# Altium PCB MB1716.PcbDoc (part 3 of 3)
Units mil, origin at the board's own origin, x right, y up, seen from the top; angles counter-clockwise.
Board outline 2806.95 x 1299.21 mil, 4 copper layers (Top Layer, M1, M2, Bottom Layer), stack 62.205 mil thick; 53 components, 45 nets, 298 pads, 399 vias.
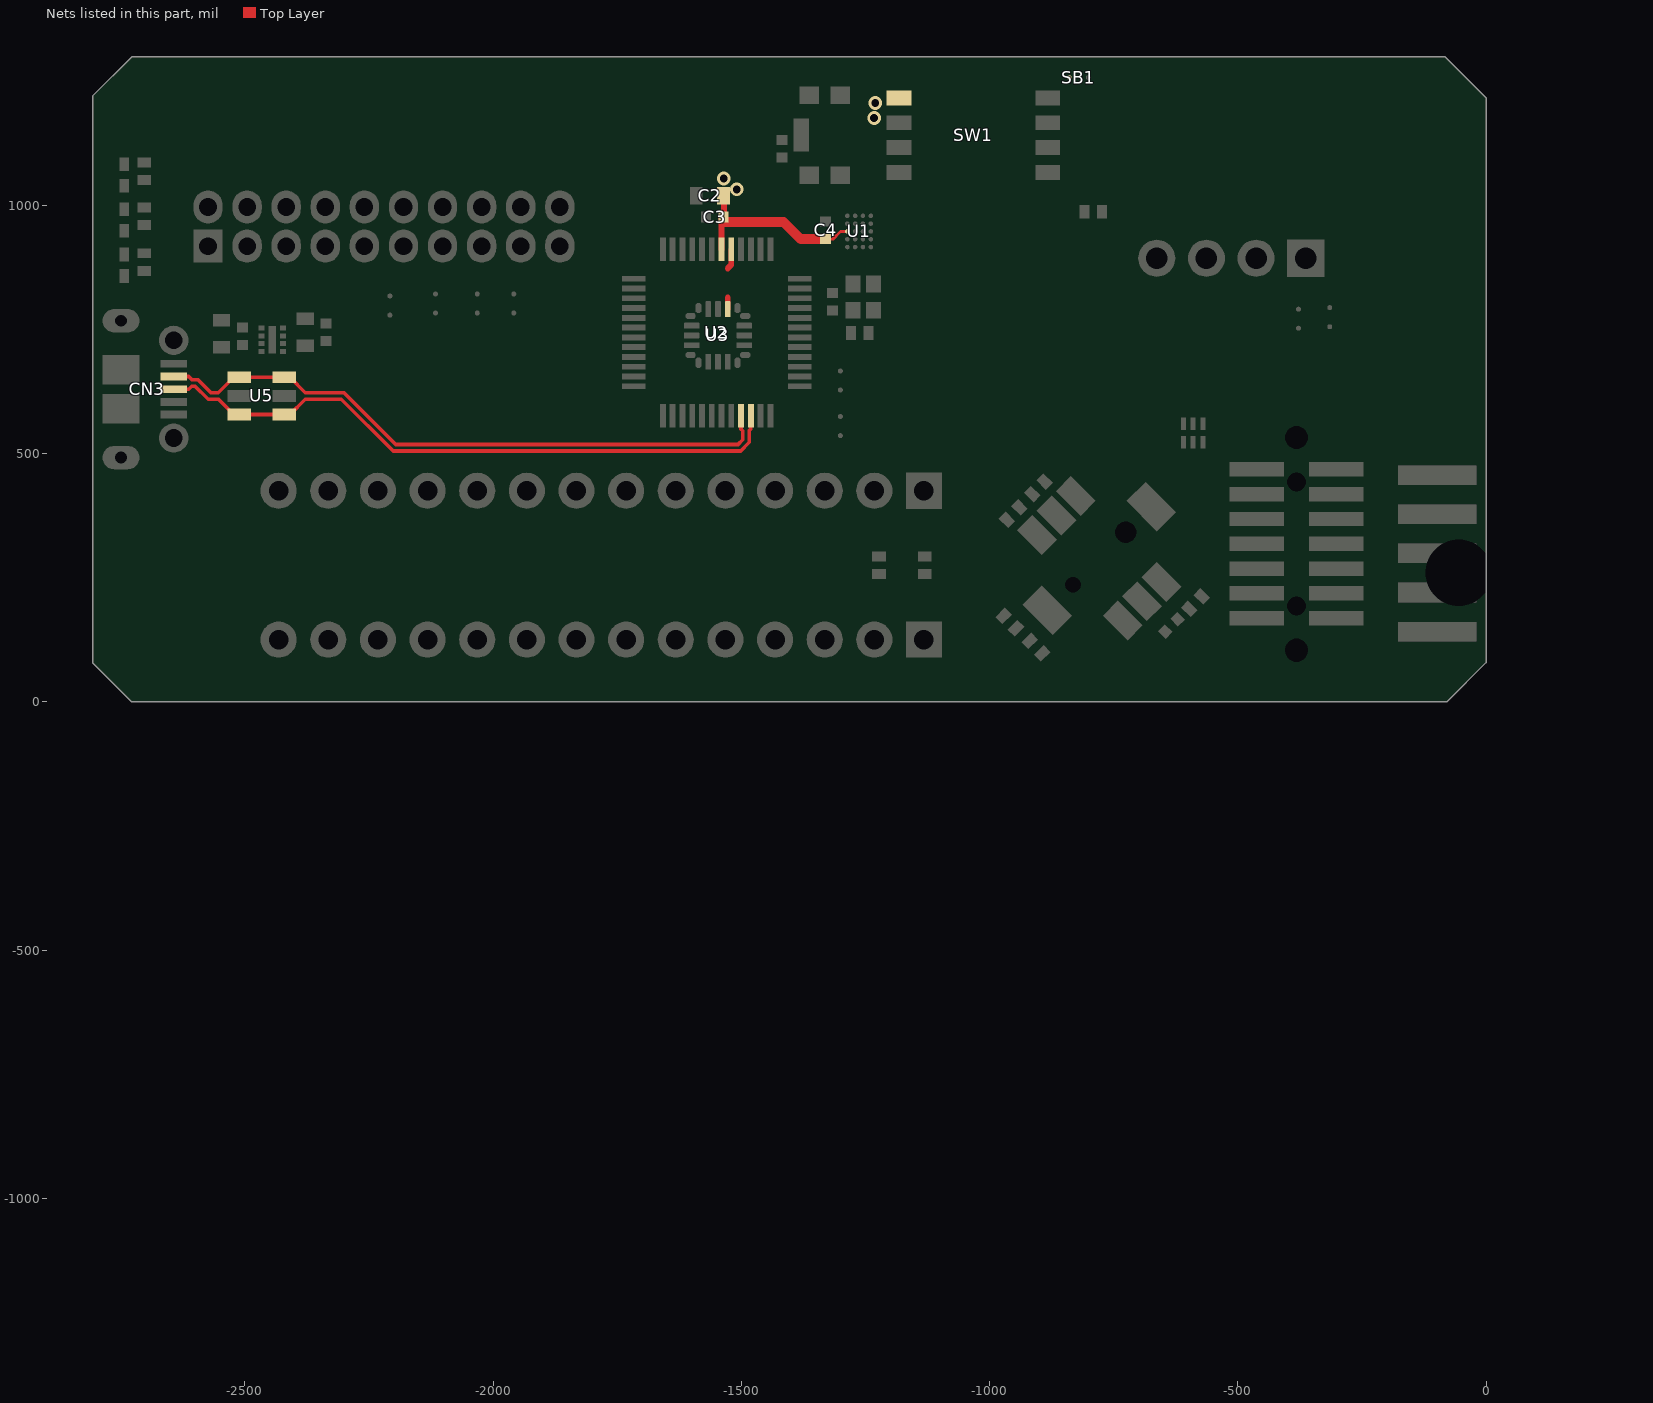
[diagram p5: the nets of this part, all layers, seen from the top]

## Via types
v1: diameter 17.72, hole 9.84, Top Layer to Bottom Layer, tented both sides, 357 vias
v2: diameter 27.56, hole 15.75, Top Layer to Bottom Layer, tented both sides, 31 vias
v3: diameter 7.87, hole 3.94, Top Layer to M1, tented both sides, 11 vias

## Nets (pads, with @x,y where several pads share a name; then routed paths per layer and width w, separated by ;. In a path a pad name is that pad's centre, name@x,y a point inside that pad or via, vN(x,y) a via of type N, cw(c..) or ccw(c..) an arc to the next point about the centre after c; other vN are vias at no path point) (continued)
USBD_N: CN3.2 U2.33 U5.3 U5.4 | length 1282.8
  Top Layer w7.28: CN3.2@-2643.56,655.51 -2613.34,655.51 -2607.14,649.31 -2595.18,649.31 -2568.58,622.72 -2553.9,622.72 -2522.87,653.74 U5.4@-2511.34,653.74 U5.3@-2420.79,653.74 -2409.25,653.74 -2378.45,622.93 -2300.5,622.93 -2196.11,518.54 -1506.92,518.54 -1497.13,528.34 -1497.13,545.93 -1500.7,549.51 U2.33@-1500.7,576.77
USBD_P: CN3.3 U2.34 U5.1 U5.6 | length 1304.2
  Top Layer w7.28: CN3.3@-2643.56,629.92 -2613.34,629.92 -2607.14,636.12 -2600.64,636.12 -2574.05,609.53 -2553.46,609.53 -2522.87,578.94 U5.6@-2511.34,578.94 U5.1@-2420.79,578.94 -2409.25,578.94 -2378.45,609.74 -2305.96,609.74 -2201.57,505.35 -1501.46,505.35 -1483.94,522.87 -1483.94,546.59 -1481.02,549.51 U2.34@-1481.02,576.77
VDD: C2.2 C3.2 C4.2 SB1.2 SW1.5 U1.C4 U2.5 U2.6 U3.2 | length 445.8
  Top Layer w4.72: U1.C4@-1286.59,947.74 U1.C4@-1284.5,947.74
  Top Layer w5.91: C4.2@-1332.52,931.89 -1316.05,931.89 -1300.2,947.74 U1.C4@-1286.59,947.74
  Top Layer w11.81: U2.6@-1540.07,911.42 C3.2@-1540.07,975.67 ; C3.2@-1530.18,971.75 -1534.88,976.46 -1534.88,1011.45 C2.2@-1529.68,1016.65 ; U3.2@-1527.56,791.34 -1527.56,814.88 ; -1527.56,873.39 -1520.39,880.56 U2.5@-1520.39,911.42
  Top Layer w19.68: C3.2@-1535.08,966.85 -1415.04,966.85 -1380.67,932.48 C4.2@-1335.91,932.48
  other v2: -1509.33,1032.48 -1535.59,1054.45 -1232.64,1176.06 -1230.55,1206.46
pads on no net: B2.NPTH1 B2.NPTH2 CN3.4 CN4.0 CN4.2 CN4.5 CN5.0 CN5.8 CN5.9 CN5.10 CN5.11 CN6.9 CN6.10 CN7.8 U2.1 U2.4 U2.8 U2.9 U2.24 U2.25 U2.26 U2.27 U5.5

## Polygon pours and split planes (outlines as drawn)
3V3 on M2 "net" (solid, remove dead copper, pour order 8): -730.67,1202.64 -762.79,1234.76 -797.24,1234.76 -806.93,1225.08 -806.93,1177.93 -755,1126 -748,1126 -730.67,1143.33
3V3 on M2 "net" (solid, remove dead copper, pour order 54): -436.81,780.24 -290.59,780.24 -193.15,682.8 -193.15,514.88 -165.59,487.32 -165.59,226.61 -207.99,184.21 -225.04,184.21 -243.9,203.07 -243.9,241.02 -207.2,277.72 -207.2,460.94 -242.99,496.73 -242.99,667.01 -307.4,731.42 -449.48,731.42
3V3 on M2 "net" (solid, remove dead copper, pour order 26): -2346.69,738.27 -2297.52,738.27 -2287.05,727.8 -2287.05,630.16 -2183.78,526.89 -809.88,526.89 -775,561.77 -775,1194.37 -745.71,1194.37 -730.67,1179.33 -730.67,789.65 -721.06,780.04 -343.7,780.04 -322.36,758.7 -322.36,753.39 -344.13,731.61 -721.06,731.61 -730.67,722.01 -730.67,539.96 -787.68,482.95 -2215.68,482.95 -2352.99,620.26 -2352.99,731.97
VDD on M2 "net" (solid, remove dead copper, pour order 40): -1553.98,1012.8 -1542.91,1001.73 -1500.12,1001.73 -1492.05,1009.8 -1492.05,1153.74 -1462.72,1183.07 -1265.75,1183.07 -1240.79,1158.11 -1223.23,1158.11 -1212.8,1168.54 -1212.8,1216.69 -1219.45,1223.35 -1513.82,1223.35 -1553.98,1183.19
DEMO_3V3 on M2 "net" (solid, remove dead copper, pour order 58): -2699.34,1130.47 -2666.61,1163.19 -1685.71,1163.19 -1614.13,1234.76 -1174.17,1234.76 -1148.5,1209.09 -1148.5,1152.95 -1133.19,1137.64 -1088.82,1137.64 -842.6,891.42 -842.6,579.65 -833.03,570.08 -813.86,570.08 -804.68,579.25 -804.68,920.67 -1148.98,1264.96 -1629.69,1264.96 -1698.66,1195.98 -2681.42,1195.98 -2720.59,1156.81 -2720.59,1142.24 -2711.67,1133.33
5V on M2 "net" (solid, remove dead copper, pour order 44): -790.12,74.76 -738.62,23.27 -320.24,23.27 -265.43,78.07 -237.68,78.07 -218.19,97.56 -218.19,132.05 -227.32,141.18 -308.15,141.18 -317.99,131.34 -317.99,93.15 -346.61,64.53 -691.38,64.53 -732.12,105.27 -732.12,254.49 -752.32,274.69 -790.12,274.68
5V on M2 "net" (solid, remove dead copper, pour order 34): -2243.12,960.76 -2223.12,980.76 -2223.12,1051.19 -2275.59,1103.66 -2660.47,1103.66 -2746.85,1017.28 -2746.85,851.14 -2669.76,774.06 -2626.42,774.06 -2601.73,749.37 -2601.73,400.31 -2451.3,249.88 -932,249.88 -895.12,286.76 -826.12,286.76 -790.12,250.76 -452.12,250.76 -274.57,428.31 -274.57,634.72 -304.84,665 -351.5,665 -360.94,655.55 -360.94,633.74 -318.23,591.02 -318.23,453.65 -466.72,305.16 -750.09,305.16 -793.7,348.76 -924.12,348.76 -975.12,297.76 -2418.04,297.76 -2551.12,430.84 -2551.12,765.25 -2603.78,817.91 -2655.28,817.91 -2699.61,862.24 -2699.61,1000.94 -2640.2,1060.35 -2313.39,1060.35 -2297.4,1044.37 -2297.4,977.09 -2280.32,960 -2240.91,960
GND on M2 "net" (solid, remove dead copper, pour order 60): -2810.59,758.46 -2810.59,1216.83 -2728.21,1299.21 -82.13,1299.21 0,1217.08 0,70.08 -78.35,-8.27 -2719.94,-8.27 -2812.64,84.43 -2812.64,764.29
GND on Bottom Layer "net" (solid, remove dead copper, pour order 62): -2810.59,758.46 -2810.59,1216.83 -2728.21,1299.21 -82.13,1299.21 0,1217.08 0,70.08 -78.35,-8.27 -2719.94,-8.27 -2812.64,84.43 -2812.64,764.29
GND on M1 "net" (solid, remove dead copper, pour order 2): -2810.59,758.46 -2810.59,1216.83 -2728.21,1299.21 -82.13,1299.21 0,1217.08 0,70.08 -78.35,-8.27 -2719.94,-8.27 -2812.64,84.43 -2812.64,764.29
GND on Top Layer "net" (solid, remove dead copper, pour order 0): -2810.59,758.46 -2810.59,1216.83 -2728.21,1299.21 -82.13,1299.21 0,1217.08 0,70.08 -78.35,-8.27 -2719.94,-8.27 -2812.64,84.43 -2812.64,764.29

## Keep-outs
Keep-Out Layer:
  lines w7.87: -1179.6,866.34 cw(c-1140.23,866.34) -1140.23,905.71 -965.04,905.71 ; -1179.6,866.34 -1179.6,594.68 ccw(c-1140.23,594.68) -1140.23,555.31 -965.04,555.32 ccw(c-965.04,594.68) -925.67,594.68 ; -1179.6,866.34 -1179.6,866.34 ; -965.04,905.71 cw(c-965.04,866.34) -925.67,866.34 -925.67,594.69 ; -965.04,905.71 -965.04,905.71 ; -925.67,594.68 -925.67,594.69 ; -2806.95,78.74 -2806.95,748.03 -2806.95,1220.47 -2728.21,1299.21 -82.13,1299.21 0,1217.08 0,1123.07 0,79.21 -79.21,0 -2491.99,0 -2728.21,0 -2806.95,78.74
  text "Keep-Out Layer" at -2526.54,-1039.84 h118.11
  text ".GKO" at -885.02,-1039.84 h118.11
M1-Board Shape:
  lines w7.87: -1179.6,866.34 cw(c-1140.23,866.34) -1140.23,905.71 -965.04,905.71 ; -1179.6,866.34 -1179.6,866.34 ; -1179.6,866.34 -1179.6,594.68 ccw(c-1140.23,594.68) -1140.23,555.31 -965.04,555.32 ccw(c-965.04,594.68) -925.67,594.68 ; -965.04,905.71 cw(c-965.04,866.34) -925.67,866.34 -925.67,594.69 ; -965.04,905.71 -965.04,905.71 ; -925.67,594.68 -925.67,594.69

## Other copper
Top Layer:
  region net 5V: -2668.82,691.06 -2625.55,691.06 -2601.18,715.43 -2601.18,726.85 -2588.31,739.72 -2524.68,739.72 -2520.59,735.63 -2487.44,735.63 -2480.12,742.95 -2460.16,742.95 -2460.16,732.17 -2460.59,731.73 -2471.85,731.73 -2472.56,731.02 -2472.56,728.27 -2471.73,727.44 -2461.14,727.44 -2460.43,726.73 -2460.43,716.57 -2470.94,716.57 -2472.56,714.96 -2472.56,713.46 -2470.12,711.02 -2460.43,711.02 -2460.43,701.34 -2463.82,697.95 -2546.14,697.95 -2577.8,666.3 -2608.07,666.3 -2612.83,671.06 -2669.25,671.06 -2672.01,673.82 -2672.01,688.39 -2668.82,691.57
  region net NetCN2_1: -328.62,784.7 -348.29,804.37 -387.68,804.37 -387.68,877.95 -334.76,930.87 -325.16,930.87 -292.2,897.91 -292.2,793.56 -301.06,784.7
  region net GND: -609.29,607.79 -609.29,587.05 -597.68,575.43 -597.68,547.72 -594.57,544.61 -583.82,544.61 -581.85,546.57 -581.85,576.46 -572.17,586.14 -572.17,608.27 -578.11,614.21 -602.87,614.21
  region net VDD: -1558.03,1061.93 -1558.03,1003.07 -1546.34,991.38 -1546.34,936.26 -1541.93,931.85 -1534.02,931.85 -1531.97,933.9 -1528.66,933.9 -1526.5,931.73 -1517.8,931.73 -1512.01,937.52 -1512.01,982.99 -1492.6,1002.4 -1492.6,1056.38 -1507.56,1071.34 -1548.62,1071.34
  region net GND: -1381.06,974.76 -1381.06,960.24 -1375.71,954.88 -1309.96,954.88 -1305.91,958.94 -1286.3,958.94 -1286.3,967.6 -1286.65,967.95 -1307.87,967.95 -1319.17,979.25 -1376.57,979.25
  region net VDD: -1335.55,942.6 -1313.86,942.6 -1304.25,952.2 -1286.38,952.2 -1286.38,943.9 -1287.01,943.27 -1295.14,943.27 -1315.77,922.64 -1326.06,922.64 -1335.91,932.48
  region net 3V3: -2429.29,727.19 -2405.84,727.19 -2394.92,738.11 -2296.18,738.11 -2289.8,731.73 -2289.8,685.87 -2298.9,676.77 -2347.6,676.77 -2366.3,695.47 -2424.29,695.47 -2429.53,700.71 -2429.53,710.98 -2418.66,711.18 -2417.68,712.17 -2417.68,715.35 -2419.06,716.73 -2428.58,716.73 -2429.29,717.2
  region net 3V3: -451.91,771.91 -390.1,771.91 -383.21,765.02 -370.87,765.02 -363.98,771.91 -363.98,742.87 -374.45,732.4 -445.79,732.4 -455.08,741.69 -455.08,768.74
  region net 5V: -314.84,771.91 -307.95,765.02 -301.06,765.02 -291.65,755.61 -291.65,643.66 -306.38,628.94 -354.76,628.94 -361.54,635.71 -361.54,667.72 -338.94,690.31 -338.94,755.94 -329.02,765.87 -320.89,765.87
  region net DEMO_3V3: -1208.66,1154.17 -1208.66,1182.28 -1206.97,1183.98 -1085.75,1183.98 -1077.2,1175.43 -1077.2,1152.13 -1090.2,1139.13 -1137.8,1139.13 -1149.13,1150.47 -1207.28,1150.47 -1208.27,1151.46 -1208.27,1180.04
  region net GND: -1566.69,915.71 -1566.69,879.17 -1586.5,859.37 -1586.5,837.91 -1563.86,815.28 -1559.33,815.28 -1554.53,810.47 -1554.53,775.39 -1552.83,773.7 -1543.46,773.7 -1540.67,776.5 -1540.67,815.9 -1552.83,828.07 -1552.83,984.49 -1569.8,1001.46 -1569.8,1058.39 -1577.64,1066.22 -1604.88,1066.22 -1631.18,1039.92 -1631.18,977.95 -1598.86,945.63 -1573.98,945.63 -1566.38,938.03 -1566.38,925.04
  region net VDD: -1546.38,940.79 -1546.38,828.58 -1533.5,815.71 -1533.5,775.31 -1532.2,774.02 -1521.14,774.02 -1519.61,775.55 -1519.61,819.69 -1528.86,828.94 -1528.86,862.48 -1512.01,879.33 -1512.01,937.52 -1520.71,937.52 -1526.54,931.69 -1526.54,887.95 -1528.62,885.87 -1531.69,885.87 -1534.06,888.23 -1534.06,936.24 -1538.6,940.79
  pour cut-out: -663.25,846.05 -663.25,916.16 -638.06,941.35 -474.38,941.35 -473.09,940.06 -473.09,847.34 -474.38,846.05
  pour cut-out: -348.78,722.37 -344.29,726.85 -380.35,726.85 -387.36,733.86 -466.1,733.86 -466.1,723.86 -464.61,722.37
  region net NetCN2_1: -400.47,909.65 -400.47,790.69 -391.54,781.75 -335.51,781.75 -328.62,774.86 -318.78,784.7 -301.06,784.7 -301.06,774.86 -292.2,783.72 -292.2,897.91 -325.16,930.87 -379.25,930.87
  pour cut-out: -281.62,755.61 -281.62,899.26 -290.51,908.15 -290.51,753.7 -285.04,748.23
  region net 5V: -175.91,161.5 -240.7,161.5 -262.55,183.35 -353.58,183.35 -356.61,180.31 -356.61,152.99 -302.68,99.06 -231.81,99.06 -208.78,122.09 -168.03,122.09 -168.03,153.62
  pour cut-out: -237.18,492.79 -1.3,492.79 -1.3,167.56 -202.01,167.56 -220.2,167.56 -265.08,212.44 -265.08,464.89
  pour cut-out: -2678.67,1139.95 -2678.67,915.24 -2721.22,915.24 -2721.22,1139.95
  region net GND: -2574.65,749.76 -2521.45,749.76 -2515.71,744.02 -2489.29,744.02 -2485.32,747.99 -2453.7,747.99 -2448.94,743.23 -2437.36,754.8 -2437.36,764.75 -2442.18,769.57 -2442.18,790.05 -2458.78,806.65 -2580.55,806.65 -2583.86,803.35 -2583.86,764.72 -2582.32,763.19
  region net GND: -2405.59,784.86 -2405.59,751.85 -2414.76,742.68 -2433.5,742.68 -2438.46,747.64 -2445.16,740.94 -2445.16,728.46 -2442.44,725.75 -2437.83,725.75 -2431.46,732.13 -2409.8,732.13 -2393.98,747.95 -2314.96,747.95 -2307.17,755.75 -2307.17,791.69 -2329.53,814.06 -2407.95,814.06 -2414.02,807.99
  pour cut-out: -2574.47,1040.5 -1866.8,1040.5 -1852.24,1025.94 -1852.24,874.8 -2613.84,874.8 -2613.84,996.85 -2574.47,996.85
  region net GND: -1269.29,875.39 -1269.29,867.09 -1267.17,864.96 -1255.39,864.96 -1248.23,857.8 -1219.49,857.8 -1210.35,866.93 -1210.35,892.99 -1214.61,892.99 -1229.09,878.5 -1267.13,878.5 -1268.5,877.13
  region net 3V3: -355.51,232.95 -238.23,232.95 -223.78,247.4 -208.82,247.4 -200,238.58 -200,193.62 -207.56,186.06 -227.4,186.06 -243.9,202.56 -356.57,202.56 -357.56,203.54 -357.56,230.91
  region net GND: -2607.14,616.5 -2607.14,596.83 -2616.34,587.64 -2674.02,587.64 -2682.91,596.54 -2692.13,587.32 -2692.13,568.7 -2686.55,568.7 -2674.15,556.3 -2659.33,556.3 -2647.32,544.29 -2643.31,548.31 -2620.96,548.31 -2608.91,560.35 -2589.33,560.35 -2589.33,573.31 -2581.61,581.02
  region net VDD: -820.33,1271.42 -826.63,1277.72 -966.73,1277.72 -1001.97,1242.48 -1227.28,1242.48 -1251.81,1217.95 -1251.81,1172.38 -1237.86,1158.42 -1221.26,1158.42 -1215.59,1164.09 -1215.59,1188.94 -1208.27,1196.26 -986.97,1196.26 -945.71,1237.52 -826.67,1237.52 -820.33,1243.86 -827.22,1250.75 -827.22,1264.53
  region net 3V3: -817,1232 -810.49,1238.51 -810.49,1250.75 -817.38,1257.64 -810.49,1264.53 -810.49,1271.42 -775.42,1271.42 -766,1262 -766,1167 -781.54,1151.46 -908.33,1151.46 -909,1152.13 -909,1181.94 -907,1183.94 -863.06,1183.94 -860,1187 -860,1197 -864,1201 -907,1201 -909,1203 -909,1231.5 -908.5,1232
  text "Top Layer" at -2526.54,-1039.84 h118.11
  text ".GTL" at -885.02,-1039.84 h118.11
M1:
  pour cut-out: -139.45,305.16 -139.45,218.46 2.6,218.46 2.6,305.16
  pour cut-out: -2574.47,1040.5 -1865.8,1040.5 -1865.8,995.58 -1826.09,995.58 -1826.09,918.11 -1865.8,918.11 -1865.8,874.46 -2574.47,874.46 -2574.47,961.42 -2613.84,961.42 -2613.84,996.85 -2574.47,996.85
  text "M1 Layer" at -2526.54,-1039.84 h118.11
  text ".G1" at -885.02,-1039.84 h118.11
M2:
  region net 5V: -2297.4,1023.83 -2297.4,977.09 -2280.32,960 -2240.91,960 -2225.47,975.43 -2225.47,1031.93 -2263.58,1070.04
  pour cut-out: -2432.24,172.05 -1132.24,172.05 -1132.24,125.91 -1087.87,125.91 -1087.87,74.57 -2381.13,74.57 -2381.13,125.39 -2432.24,125.39
  pour cut-out: -2178.9,425.39 -2178.9,477.44 -1092.68,477.44 -1092.68,436.42 -1132.24,436.42 -1132.24,378.73 -2132.24,378.73 -2132.24,425.39
  pour cut-out: -2102.03,1040.5 -1865.8,1040.5 -1865.8,996.85 -1825.47,996.85 -1825.47,918.11 -2104.41,918.11 -2104.41,1036.97
  pour cut-out: -1893.39,714.71 -1893.39,714.52 -1847.05,714.52 -1847.05,737.72 -1884.68,737.72
  pour cut-out: -139.45,305.16 -139.45,218.46 2.6,218.46 2.6,305.16
  pour cut-out: -2527.83,1024.76 -2527.83,1053.11 -2524.25,1056.69 -2319.45,1056.69 -2307.01,1044.25 -2307.01,1010.54 -2312.31,1005.24 -2498.98,1005.24 -2518.5,1024.76
  text "M2 Layer" at -2526.54,-1039.84 h118.11
  text ".G2" at -885.02,-1039.84 h118.11
Bottom Layer:
  pour cut-out: -3.98,498.98 -226.1,498.98 ccw(c-226.1,473.74) -251.33,473.74 -251.33,122 ccw(c-232.28,122) -232.28,102.95 -16.5,102.95 ccw(c-16.5,121.57) 2.13,121.57
  region net 5V: -305.47,101.69 -227.28,101.69 -221.65,107.32 -221.65,128.38 -227.99,134.72 -303.94,134.72 -311.81,126.85 -311.81,107.76 -308.5,104.45
  pour cut-out: -567.97,519.07 -589.49,497.55 -589.49,489.45 -558.98,489.45 -555.63,486.1 -550.35,491.38 -550.35,511.77
  region net 3V3: -241.3,580.55 -241.3,473.74 -204.61,437.05 -168.86,437.05 -168.86,467.76 -176.97,475.87 -184.72,475.87 -201.18,492.32 -201.18,579.8 -209.61,588.23 -233.62,588.23
  pour cut-out: -2613.84,961.42 -2613.84,996.85 -2574.47,996.85 -2574.47,1040.5 -1865.8,1040.5 -1865.8,993.75 -1826.09,993.75 -1826.09,851.02 -1877.99,851.02 -1877.99,874.46 -2613.15,874.46 -2613.15,958.46
  pour cut-out: -2232.24,78.73 -2132.24,78.73 -2132.24,108.89 -2151.3,127.95 -2229.68,127.95 -2232.24,125.39
  pour cut-out: -1167.49,172.05 -1137.95,142.52 -1178.5,101.97 -1178.5,79.13 -1753.78,79.13 -1801.38,126.73 -1801.38,172.05
  pour cut-out: -1591.68,633.08 -1523.08,633.08 -1519.53,629.53 -1519.53,591.14 -1528.5,582.17 -1537.01,590.67 -1581.1,590.67
  region net 3V3: -236.65,240.43 -236.65,193.82 -229.06,186.22 -213.31,186.22 -203.62,195.91 -203.62,238.9 -211.5,246.77 -230.59,246.77 -233.9,243.46
  region net 3V3: -448.27,738.23 -398.23,738.23 -390.91,745.55 -390.91,762.24 -399.92,771.26 -446.73,771.26 -454.61,763.39 -454.61,744.29 -451.3,740.98
  region net 5V: -355.43,629.61 -305.39,629.61 -298.07,636.93 -298.07,653.62 -307.09,662.64 -353.9,662.64 -361.77,654.76 -361.77,635.67 -358.46,632.36
  region net DEMO_3V3: -807.24,575.55 -807.24,625.59 -814.57,632.91 -831.26,632.91 -840.28,623.9 -840.28,577.09 -832.4,569.21 -813.31,569.21 -810,572.52
  region net DEMO_3V3: -1088.5,1180.28 -1138.54,1180.28 -1145.87,1172.95 -1145.87,1156.26 -1136.85,1147.24 -1090.04,1147.24 -1082.17,1155.12 -1082.17,1174.21 -1085.47,1177.52
  region net VDD: -1247.52,1217.05 -1247.52,1167.01 -1240.2,1159.69 -1223.5,1159.68 -1214.49,1168.7 -1214.49,1215.51 -1222.36,1223.39 -1241.46,1223.39 -1244.76,1220.08
  region net 3V3: -799.81,1225.69 -799.81,1175.65 -792.49,1168.33 -775.8,1168.33 -766.78,1177.35 -766.78,1224.16 -774.65,1232.03 -793.75,1232.03 -797.06,1228.72
  region net 5V: -2598.66,733.11 -2598.66,683.07 -2591.34,675.75 -2574.65,675.75 -2565.63,684.76 -2565.63,731.57 -2573.5,739.45 -2592.6,739.45 -2595.91,736.14
  region net 3V3: -2320.24,738.39 -2297.8,738.39 -2288.54,729.13 -2288.54,682.8 -2295.39,675.94 -2344.13,675.94 -2354.88,686.69 -2354.88,704.76 -2322.2,737.44
  region net VDD: -1555.08,1049.94 -1519.69,1014.56 -1501.7,1014.56 -1493.54,1022.72 -1493.54,1040.98 -1526.85,1074.29 -1539.69,1074.29 -1555.27,1058.71 -1555.27,1054.03
  text ".GBL" at -1326.09,-1041.1 h118.11
  text "Bottom Layer" at 300.45,-1041.1 h118.11

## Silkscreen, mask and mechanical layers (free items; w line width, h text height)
Top Overlay:
  lines w3.94: -234.31,217.99 -209.7,229.8 -209.7,206.18 -233.19,217.44
  lines w5: -893.12,640.35 -894.21,639.25 ; -876.12,639.25 -894.21,639.25 ; -894.21,639.25 -894.21,1005.09 ; -894.21,1005.09 -892.78,1005.09 -876.12,988.43 -909.94,988.43 -894.21,1004.15 -894.21,1005.09
  lines w10: -2495.24,175.39 -2495.24,375.39 -1082.24,375.39 -1082.24,300.39 ccw(c-1081.76,275.39) -1082.24,250.39 -1082.24,175.39 -2495.24,175.39
  text "Reset" at -1422.18,1172.38 h55.12 r90
  text "BlueTooth" at -283.37,1106.73 h55.12
  text "STMod+" at -1800.65,1092.77 h55.12
  text "GND" at -112.9,1005.09 h55.12 r90
  text "3V3" at -425.06,814.72 h55.12
  text "5V" at -335.9,814.72 h55.12
  text "IDD" at -871.46,778.58 h55.12
  text "ON" at -738.09,775.4 h55.12
  text "GND" at -467.17,739.07 h55.12 r90
  text "Demo" at -871.46,727.72 h55.12
  text "ON" at -738.09,724.78 h55.12
  text "BT_RX" at -622.29,714.57 h55.12 r90
  text "BT_TX" at -541.69,715.04 h55.12 r90
  text "RXSL" at -871.46,676.87 h55.12
  text "ON" at -738.09,674.16 h55.12
  text "MB1716A" at -146.26,631.57 h80 r90
  text "32K" at -871.46,626.72 h55.12
  text "OFF" at -758,624.23 h55.12
  text "STDC14" at -467.17,590.59 h55.12
  text "BTB_10" at -169.99,513.43 h55.12
  text "NRST" at -1169.21,482.46 h55.12
  text "D8" at -2412.6,481.85 h55.12 r90
  text "D7" at -2315.51,481.85 h55.12 r90
  text "D6" at -2219.57,481.85 h55.12 r90
  text "D5" at -2116.46,481.85 h55.12 r90
  text "GND" at -1816.69,481.85 h55.12 r90
  text "5V" at -1715.39,481.85 h55.12 r90
  text "D4" at -1611.65,481.85 h55.12 r90
  text "D3" at -1512.72,481.85 h55.12 r90
  text "D2" at -1416.81,481.85 h55.12 r90
  text "D1" at -1321.65,481.85 h55.12 r90
  text "D0" at -1221.38,481.85 h55.12 r90
  text "CLK" at -181,344.8 h55.12 r90
  text "DIP28 Arduino-compatible pinout" at -2422.01,261.57 h70.87
  text "DIO" at -181.1,260.79 h55.12 r90
  text "UP" at -996.12,259.76 h55.12 r90
  text "5V" at -181.1,118.86 h55.12 r90
  text "J" at -2527.83,64.33 h500 r90
  text "5V" at -1971.38,31.5 h55.12 r45
  text "A1" at -1572.87,32 h55.12 r45
  text "D9" at -2486.61,30.31 h55.12 r45
  text "A2" at -1471.06,30.34 h55.12 r45
  text "A3" at -1385.04,30.78 h55.12 r45
  text "A4" at -1282.32,30.31 h55.12 r45
  text "A5" at -1192.8,31.14 h55.12 r45
  text "A0" at -1683.46,30.27 h55.12 r45
  text "D11" at -2297.01,14.37 h55.12 r45
  text "D10" at -2399.72,12.64 h55.12 r45
  text "D12" at -2195.2,12.71 h55.12 r45
  text "D13" at -2098.66,13.14 h55.12 r45
  text "GND" at -1816.61,11.93 h55.12 r45
  text "Top Overlay" at -2526.54,-1039.84 h118.11
  text ".GTO" at -885.02,-1039.84 h118.11
Bottom Overlay:
  text "E" at -498.27,1039.84 h400
  text "S" at -200.63,1015.16 h400
  text "I" at -1772.72,632.68 h400
  text "C" at -620.59,613.35 h400
  text "H" at -353.62,609.84 h400
  text "G" at -2232.87,578.23 h400
  text "F" at -1992.24,578.23 h400
  text "GND" at -1847.68,489.68 h55.12 r270
  text "NRST" at -1083.9,488.35 h55.12
  text "D8" at -2447.56,487.68 h55.12 r270
  text "D7" at -2345.24,487.68 h55.12 r270
  text "D6" at -2244.88,487.68 h55.12 r270
  text "D5" at -2146.61,487.68 h55.12 r270
  text "5V" at -1747.32,487.68 h55.12 r270
  text "D4" at -1640.94,487.68 h55.12 r270
  text "D3" at -1548.03,487.68 h55.12 r270
  text "D1" at -1346.69,487.68 h55.12 r270
  text "D0" at -1251.1,487.68 h55.12 r270
  text "D2" at -1450,486.81 h55.12 r270
  text "3V3" at -198.31,443.58 h62.99
  text "NRST" at -198.31,360.32 h62.99
  text "TX" at -198.31,282.64 h62.99
  text "RX" at -198.31,206.1 h62.99
  text "GND" at -198.31,123.94 h62.99
  text "D9" at -2408.98,30.32 h55.12
  text "D10" at -2298.74,30.32 h55.12
  text "D13" at -1994.92,30.32 h55.12
  text "5V" at -1907.99,30.32 h55.12
  text "GND" at -1687.56,30.32 h55.12
  text "A0" at -1607.8,30.32 h55.12
  text "A3" at -1305.79,30.32 h55.12
  text "A5" at -1106.85,30.32 h55.12
  text "D11" at -2200.16,29.61 h55.12
  text "D12" at -2100.67,29.61 h55.12
  text "A1" at -1511.02,29.61 h55.12
  text "A2" at -1407.05,29.61 h55.12
  text "A4" at -1204.38,29.61 h55.12
  text ".GBO" at -1326.09,-1041.1 h118.11
  text "Bottom Overlay" at 300.45,-1041.1 h118.11
Top Paste:
  text "Top Paste" at -2526.54,-1039.84 h118.11
  text ".GTP" at -885.02,-1039.84 h118.11
Bottom Paste:
  text ".GBP" at -1326.09,-1041.1 h118.11
  text "Bottom Paste" at 300.45,-1041.1 h118.11
Top Solder:
  region: -84.61,1289.75 -84.61,622.95 -11.63,622.95 -11.63,1216.77
  text "Top Solder" at -2526.54,-1039.84 h118.11
  text ".GTS" at -885.02,-1039.84 h118.11
Bottom Solder:
  region: -158.46,1291.34 -158.46,622.95 -11.63,622.95 -11.63,1216.77 -86.2,1291.34
  text ".GBS" at -1326.09,-1041.1 h118.11
  text "Bottom Solder" at 300.45,-1041.1 h118.11
M1-Board Shape:
  lines w7.87: 0,79.57 0,247.95 -110.24,247.95 cw(c-110.24,259.76) -110.24,271.57 0,271.57 ; -2806.95,78.74 -2728.21,0 ; -2806.95,78.74 -2806.95,748.03 ; -2806.95,78.74 -2728.21,0 ; -2806.95,78.74 -2806.95,748.03 ; -2806.95,748.03 -2806.95,1220.47 ; -2806.95,748.03 -2806.95,1220.47 ; -2806.95,1220.47 -2728.21,1299.21 ; -2806.95,1220.47 -2728.21,1299.21 ; -2728.21,0 -2491.99,0 ; -2728.21,0 -2491.99,0 ; -2728.21,1299.21 -82.13,1299.21 ; -2728.21,1299.21 -82.13,1299.21 ; -2491.99,0 -79.21,0 ; -2491.99,0 -79.21,0 ; -82.13,1299.21 0,1217.08 ; -82.13,1299.21 0,1217.08 ; -79.21,0 0,79.21 -79.21,0 ; 0,271.57 0,1217.08 ; 0,271.57 0,1217.08
M2-Board Dimensions:
  text "M2-Board Dimensions" at -2526.54,-1039.84 h118.11
  text ".GM2" at -885.02,-1039.84 h118.11
M14-Top Assembly:
  lines w7.87: -79.21,0 0,0 0,79.21
  text "M14-Top Assembly" at -2526.54,-1039.84 h118.11
  text ".GM14" at -885.02,-1039.84 h118.11
M15-Bottom Assembly:
  text ".GM15" at -1326.09,-1041.1 h118.11
  text "M15-Bottom Assembly" at 300.45,-1041.1 h118.11
Drill Drawing:
  drawing of 548 lines, arcs and shapes, not listed
  text "PCB SPECIFICATIONS :" at -2936.81,3974.87 h118.11
  text "PCB : TYPE 3" at 2869.95,3968.09 h118.11
  text "A.   MATERIAL :" at -2936.81,3817.39 h118.11
  text "FR-4" at -1421.06,3817.39 h118.11
  text "TG-170" at -771.46,3817.39 h118.11
  text "X  TG-150" at -52.95,3817.39 h118.11
  text "TG-140" at 576.97,3817.39 h118.11
  text "ASPECT-RATIO, AXE Z :" at 2869.95,3751.55 h118.11
  text "B.   MATERIAL FAMILY :" at -2936.81,3699.28 h118.11
  text "N/A" at -1421.06,3699.28 h118.11
  text "C.   SOLDERMASK COLOR :" at -2936.81,3581.17 h118.11
  text "GREEN" at -1421.06,3581.17 h118.11
  text "WHITE" at -766.18,3580.35 h118.11
  text "X   BLUE" at -52.95,3581.17 h118.11
  text "BLACK" at 576.97,3581.17 h118.11
  text "6:1 to 8:1 / LEVEL \"B\"" at 2870.68,3485.9 h118.11
  text "D.   SILKSCREEN COLOR :" at -2936.81,3463.06 h118.11
  text "X   WHITE" at -1421.06,3463.06 h118.11
  text "YELLOW" at -771.46,3463.06 h118.11
  text "BLACK" at -52.95,3463.06 h118.11
  text "Blue ink PANTONE 2955" at 576.97,3463.06 h118.11
  text "E.   SURFACE FINISH :" at -2936.81,3344.95 h118.11
  text "X  ENIG" at -1421.06,3344.95 h118.11
  text "IMMERSION SILVER" at -771.46,3344.95 h118.11
  text "IMMERSION TIN" at 576.97,3344.95 h118.11
  text "MINIMUM PARAMETERS" at 2871.74,3265.39 h118.11
  text "HASL" at -1421.06,3226.84 h118.11
  text "HASL (PB-FREE)" at -771.46,3226.84 h118.11
  text "GOLDEN FINGER" at 576.97,3226.84 h118.11
  text "F.   IMPEDANCE CONTROL :" at -2936.81,3108.73 h118.11
  text "NO" at -1421.06,3108.73 h118.11
  text "X YES  (SEE IMPEDANCE TABLE FOR DETAIL INFORMATION)" at -794,3109 h118.11
  text "DEFAULT" at 2871.74,3048.86 h118.11
  text "G.   THROUGH VIA :" at -2936.81,2990.62 h118.11
  text "PLUG THE VIAS WHICH ARE COVERED WITH SOLDERMASK ONE OR TWO SIDE." at -1421.06,2990.62 h118.11
  text "PLUG MATERIAL :" at -1421.06,2872.51 h118.11
  text "X  SOLDERMASK" at -417.13,2872.51 h118.11
  text "NON-CONDUCTIVE EPOXY." at 576.97,2872.51 h118.11
  text "TRACKS : 0.12mm           / GAPS : 0.12mm" at 2871.74,2822.48 h118.11
  text "H.   STACK-UP :" at -2936.81,2754.4 h118.11
  text "SEE LAYER STACK-UP SEQUENCE FOR OVERALL THICKNESS." at -1421.06,2754.4 h118.11
  text "Symbol" at 1223.73,2449.76 h85.04
  text "Count" at 1557.06,2449.76 h85.04
  text "Hole Size" at 1904.72,2449.76 h85.04
  text "Plated" at 2548.07,2449.76 h85.04
  text "Hole Type" at 2840.73,2449.76 h85.04
  text "Drill Layer Pair" at 3266.61,2449.76 h85.04
  text "Via/Pad" at 4073.82,2449.76 h85.04
  text "Pad Shape" at 4422.92,2449.76 h85.04
  text "Template" at 4878.84,2449.76 h85.04
  text "IMPEDANCE TABLE     USB" at -2945.61,2402.28 h118.11
  text "1" at 1557.06,2302.71 h70.87
  text "31.50mil (0.80mm)" at 1904.72,2302.71 h70.87
  text "NPTH" at 2548.07,2302.71 h70.87
  text "Round" at 2840.73,2302.71 h70.87
  text "Top Layer - Bottom Layer" at 3266.61,2302.71 h70.87
  text "Pad" at 4073.82,2302.71 h70.87
  text "Rounded" at 4422.92,2302.71 h70.87
  text "c0hn80m85p1000" at 4878.84,2302.71 h70.87
  text "LAYER" at -2778.28,2205.42 h118.11
  text "TRACE" at -2138.52,2205.42 h118.11
  text "SPACING" at -1725.13,2205.42 h118.11
  text "IMPEDANCE" at -1193.64,2205.42 h118.11
  text "IMPEDANCE" at -524.35,2205.42 h118.11
  text "TOL." at 213.84,2205.43 h118.11
  text "1" at 1557.06,2155.66 h70.87
  text "43.31mil (1.10mm)" at 1904.72,2155.66 h70.87
  text "NPTH" at 2548.07,2155.66 h70.87
  text "Round" at 2840.73,2155.66 h70.87
  text "Top Layer - Bottom Layer" at 3266.61,2155.66 h70.87
  text "Pad" at 4073.82,2155.66 h70.87
  text "Rounded" at 4422.92,2155.66 h70.87
  text "c0hn110m115p1000" at 4878.84,2155.66 h70.87
  text "(mm)" at -1594.23,2107.98 h98.43
  text "(mm)" at -2059.78,2106.02 h98.43
  text "(Single ended)" at -1173.95,2097.16 h98.43
  text "(Differential)" at -475.13,2097.16 h98.43
  text "1" at 1557.06,2008.61 h70.87
  text "133.86mil (3.40mm)" at 1904.72,2008.61 h70.87
  text "NPTH" at 2548.07,2008.61 h70.87
  text "Slot" at 2840.73,2008.61 h70.87
  text "Top Layer - Bottom Layer" at 3266.61,2008.61 h70.87
  text "Pad" at 4073.82,2008.61 h70.87
  text "Rounded" at 4422.92,2008.61 h70.87
  text "c0hn340_60m345" at 4878.84,2008.61 h70.87
  text "0.185" at -2100.13,1950.5 h118.11
  text "NA" at -973.17,1950.5 h118.11
  text "0.15" at -1626.71,1949.52 h118.11
  text "90 ohm" at -396.39,1949.52 h118.11
  text "+/- 10%" at 154.79,1949.52 h118.11
  text "TOP" at -2926.71,1948.93 h118.11
  text "2" at 1557.06,1861.56 h70.87
  text "23.62mil (0.60mm)" at 1904.72,1861.56 h70.87
  text "PTH" at 2548.07,1861.56 h70.87
  text "Slot" at 2840.73,1861.56 h70.87
  text "Top Layer - Bottom Layer" at 3266.61,1861.56 h70.87
  text "Pad" at 4073.82,1861.56 h70.87
  text "Rounded" at 4422.92,1861.56 h70.87
  text "r190_120h60_130r100m195_125" at 4878.84,1861.56 h70.87
  text "2" at 1557.06,1714.51 h70.87
  text "38.19mil (0.97mm)" at 1904.72,1714.51 h70.87
  text "NPTH" at 2548.07,1714.51 h70.87
  text "Round" at 2840.73,1714.51 h70.87
  text "Top Layer - Bottom Layer" at 3266.61,1714.51 h70.87
  text "Pad" at 4073.82,1714.51 h70.87
  text "Rounded" at 4422.92,1714.51 h70.87
  text "c0hn97m102" at 4878.84,1714.51 h70.87
  text "2" at 1557.06,1567.46 h70.87
  text "46.85mil (1.19mm)" at 1904.72,1567.46 h70.87
  text "NPTH" at 2548.07,1567.46 h70.87
  text "Round" at 2840.73,1567.46 h70.87
  text "Top Layer - Bottom Layer" at 3266.61,1567.46 h70.87
  text "Pad" at 4073.82,1567.46 h70.87
  text "Rounded" at 4422.92,1567.46 h70.87
  text "c0hn119m124" at 4878.84,1567.46 h70.87
  text "4" at 1557.06,1420.41 h70.87
  text "43.31mil (1.10mm)" at 1904.72,1420.41 h70.87
  text "PTH" at 2548.07,1420.41 h70.87
  text "Round" at 2840.73,1420.41 h70.87
  text "Top Layer - Bottom Layer" at 3266.61,1420.41 h70.87
  text "Pad" at 4073.82,1420.41 h70.87
  text "(Mixed)" at 4422.92,1420.41 h70.87
  text "(Mixed)" at 4878.84,1420.41 h70.87
  text "11" at 1557.06,1273.36 h70.87
  text "3.94mil (0.10mm)" at 1904.72,1273.36 h70.87
  text "PTH" at 2548.07,1273.36 h70.87
  text "Round" at 2840.73,1273.36 h70.87
  text "Top Layer - M1" at 3266.61,1273.36 h70.87
  text "Via" at 4073.82,1273.36 h70.87
  text "Rounded" at 4422.92,1273.36 h70.87
  text "v20h10m0" at 4878.84,1273.36 h70.87
  text "22" at 1557.06,1126.31 h70.87
  text "35.43mil (0.90mm)" at 1904.72,1126.31 h70.87
  text "PTH" at 2548.07,1126.31 h70.87
  text "Round" at 2840.73,1126.31 h70.87
  text "Top Layer - Bottom Layer" at 3266.61,1126.31 h70.87
  text "Pad" at 4073.82,1126.31 h70.87
  text "(Mixed)" at 4422.92,1126.31 h70.87
  text "(Mixed)" at 4878.84,1126.31 h70.87
  text "28" at 1557.06,979.26 h70.87
  text "39.37mil (1.00mm)" at 1904.72,979.26 h70.87
  text "PTH" at 2548.07,979.26 h70.87
  text "Round" at 2840.73,979.26 h70.87
  text "Top Layer - Bottom Layer" at 3266.61,979.26 h70.87
  text "Pad" at 4073.82,979.26 h70.87
  text "Rounded" at 4422.92,979.26 h70.87
  text "(Mixed)" at 4878.84,979.26 h70.87
  text "31" at 1557.06,832.21 h70.87
  text "15.75mil (0.40mm)" at 1904.72,832.21 h70.87
  text "PTH" at 2548.07,832.21 h70.87
  text "Round" at 2840.73,832.21 h70.87
  text "Top Layer - Bottom Layer" at 3266.61,832.21 h70.87
  text "Via" at 4073.82,832.21 h70.87
  text "Rounded" at 4422.92,832.21 h70.87
  text "v70h40m0mx0" at 4878.84,832.21 h70.87
  text "357" at 1557.06,685.16 h70.87
  text "9.84mil (0.25mm)" at 1904.72,685.16 h70.87
  text "PTH" at 2548.07,685.16 h70.87
  text "Round" at 2840.73,685.16 h70.87
  text "Top Layer - Bottom Layer" at 3266.61,685.16 h70.87
  text "Via" at 4073.82,685.16 h70.87
  text "Rounded" at 4422.92,685.16 h70.87
  text "(Mixed)" at 4878.84,685.16 h70.87
  text "462 Total" at 1557.06,538.11 h70.87
  text "Slot definitions :" at 1223.73,435.18 h70.87
  text "Routed Path Length" at 1707.61,435.18 h70.87
  text "= Calculated from tool start centre position to tool end centre position." at 2306.99,435.18 h70.87
  text "Hole Length" at 1707.61,376.36 h70.87
  text "= Routed Path Length + Tool Size = Slot length as defined in the PCB layout" at 2084.51,376.36 h70.87
  text "Layer" at 1227.5,-71.5 h60
  text "Name" at 1637.41,-71.5 h60
  text "Material" at 2567.16,-71.5 h60
  text "Thickness" at 3426.92,-71.5 h60
  text "Constant" at 4076.76,-71.5 h60
  text "Board Layer Stack" at 4646.62,-71.5 h60
  text "Top Overlay" at 1637.41,-191.5 h60
  text "Top Solder" at 1637.41,-311.5 h60
  text "Solder Resist" at 2567.16,-311.5 h60
  text "0.015mm" at 3426.92,-311.5 h60
  text "3.5" at 4076.76,-311.5 h60
  text "1" at 1227.5,-431.5 h60
  text "Top Layer" at 1637.41,-431.5 h60
  text "Copper" at 2567.16,-431.5 h60
  text "0.035mm" at 3426.92,-431.5 h60
  text "Dielectric 1" at 1637.41,-551.5 h60
  text "FR-4" at 2567.16,-551.5 h60
  text "0.220mm" at 3426.92,-551.5 h60
  text "4.2" at 4076.76,-551.5 h60
  text "2" at 1227.5,-671.5 h60
  text "M1" at 1637.41,-671.5 h60
  text "Copper" at 2567.16,-671.5 h60
  text "0.035mm" at 3426.92,-671.5 h60
  text "Dielectric 3" at 1637.41,-791.5 h60
  text "1.000mm" at 3426.92,-791.5 h60
  text "4.2" at 4076.76,-791.5 h60
  text "3" at 1227.5,-911.5 h60
  text "M2" at 1637.41,-911.5 h60
  text "Copper" at 2567.16,-911.5 h60
  text "0.035mm" at 3426.92,-911.5 h60
  text "Dielectric 2" at 1637.41,-1031.5 h60
  text "0.220mm" at 3426.92,-1031.5 h60
  text "4.2" at 4076.76,-1031.5 h60
  text "Drill Drawing" at -2526.54,-1039.84 h118.11
  text ".DRL" at -885.02,-1039.84 h118.11
  text "4" at 1227.5,-1151.5 h60
  text "Bottom Layer" at 1637.41,-1151.5 h60
  text "Copper" at 2567.16,-1151.5 h60
  text "0.035mm" at 3426.92,-1151.5 h60
  text "Bottom Solder" at 1637.41,-1271.5 h60
  text "Solder Resist" at 2567.16,-1271.5 h60
  text "0.015mm" at 3426.92,-1271.5 h60
  text "3.5" at 4076.76,-1271.5 h60
  text "Bottom Overlay" at 1637.41,-1391.5 h60
M20-Top Title Box:
  circle w10: c544.49,-1304.43 r51.18
  region: -25.51,-1347.47 -448.98,-1347.47 -409.87,-1249.33 -100.51,-1249.33 -82.85,-1219.43 4.1,-1319.76
  region: 525.79,-1019.54 -85.51,-1019.54 -112.85,-1089.43 -160.51,-1137.66 -215.51,-1064.43 -215.51,-999.43 -170.51,-944.43 -113.98,-929.54 525.79,-929.54
  lines w10: -409.87,-1249.33 -63.74,-1249.33 -184.45,-1110.05 cw(c-113.43,-1033.52) -103.98,-929.54 556.02,-929.54 526.02,-1019.54 ; -279.41,-919.81 cw(c-183.89,-958.01) -174.58,-855.56 ; -277.87,-918.53 -448.98,-1347.47 311.75,-1347.47 ccw(c321.54,-1239.82) 421.91,-1279.97 ; -209.37,-1073.44 4.1,-1319.76 ; -199.37,-1073.44 9.49,-1314.43 ; -199.37,-1063.44 9.49,-1304.43 ; -195.51,-1019.54 316.02,-1019.54 ; -194.37,-1058.44 14.49,-1299.43 ; -189.37,-1053.44 19.49,-1294.43 ; -184.37,-1048.44 24.49,-1289.43 ; -179.37,-1043.44 29.49,-1284.43 ; -177.22,-966.58 31.64,-1207.57 ; -174.53,-855.57 591.21,-855.57 421.94,-1279.87 ; -174.37,-1038.44 32.34,-1276.96 ; -174.37,-1028.44 34.49,-1269.43 ; -174.37,-1018.44 34.49,-1259.43 ; -174.37,-983.44 34.49,-1224.43 ; -169.37,-1013.44 39.49,-1254.43 ; -169.37,-998.44 39.49,-1239.43 ; -115.37,-1249.86 ccw(c-111.23,-1228.78) -99.51,-1210.79 ; -72.59,-1019.01 ccw(c-73.61,-1041.35) -86.62,-1059.54 6.49,-1166.97 cw(c-64.53,-1243.5) -35.69,-1343.84 ; 174.7,-1339.43 288.46,-1009.54 ; 183.46,-1337.47 296.42,-1009.88 ; 188.46,-1337.47 301.42,-1009.88 ; 198.46,-1337.47 311.42,-1009.88 ; 208.46,-1337.47 321.42,-1009.88 ; 218.46,-1337.47 331.42,-1009.88 ; 228.46,-1337.47 341.42,-1009.88 ; 238.46,-1337.47 351.42,-1009.88 ; 248.46,-1337.47 361.42,-1009.88 ; 258.46,-1337.47 371.42,-1009.88 ; 266.67,-1339.43 380.42,-1009.54 ; 380.42,-1019.54 525.79,-1019.54 ; 499.49,-1019.43 529.49,-929.43 ; 506.02,-1019.54 536.02,-929.54 ; 516.02,-1019.54 546.02,-929.54
  lines w11.81: -2880.88,-1500.47 662.42,-1500.47 662.42,-713.07 -2880.88,-713.07 ; -2880.88,-1303.62 -518.68,-1303.62 ; -2880.88,-1106.77 -518.68,-1106.77 ; -2880.88,-909.92 -518.68,-909.92 ; -2880.87,-1500.47 -2880.87,-713.07 ; -1306.08,-1500.47 -1306.08,-909.92 ; -518.68,-1500.47 -518.68,-713.07 ; 174.7,-1339.43 266.67,-1339.43
  text "Project: '.Board_Name'" at -2841.5,-839.69 h118.11
  text "Layer:" at -2841.5,-1039.84 h118.11
  text "Gerber:" at -1267.14,-1039.84 h118.11
  text "Variant: '.VariantName'" at -2841.5,-1236.69 h118.11
  text "Ref: MB1716" at -1262.14,-1236.69 h118.11
  text "R" at 524.49,-1334.43 h60
  text "Date: 13-01-21" at -2841.5,-1433.54 h118.11
  text "Rev: A" at -1264.39,-1433.54 h118.11
M21-Bottom Title Box:
  circle w10: c-2755.57,-1304.43 r51.18
  region: -2736.88,-1019.54 -2125.57,-1019.54 -2098.24,-1089.43 -2050.57,-1137.66 -1995.57,-1064.43 -1995.57,-999.43 -2040.57,-944.43 -2097.11,-929.54 -2736.88,-929.54
  region: -2185.57,-1347.47 -1762.11,-1347.47 -1801.22,-1249.33 -2110.57,-1249.33 -2128.24,-1219.43 -2215.19,-1319.76
  lines w10: -2757.11,-929.54 -2727.11,-1019.54 ; -2747.11,-929.54 -2717.11,-1019.54 ; -2740.57,-929.43 -2710.57,-1019.43 ; -2737.11,-1019.54 -2767.11,-929.54 -2107.11,-929.54 cw(c-2097.66,-1033.52) -2026.64,-1110.05 -2147.35,-1249.33 -1801.22,-1249.33 ; -2736.88,-1019.54 -2591.51,-1019.54 ; -2633.03,-1279.87 -2802.29,-855.57 -2036.56,-855.57 ; -2632.99,-1279.97 ccw(c-2532.63,-1239.82) -2522.84,-1347.47 -1762.11,-1347.47 -1933.22,-918.53 ; -2591.51,-1009.54 -2477.76,-1339.43 ; -2582.51,-1009.88 -2469.55,-1337.47 ; -2572.51,-1009.88 -2459.55,-1337.47 ; -2562.51,-1009.88 -2449.55,-1337.47 ; -2552.51,-1009.88 -2439.55,-1337.47 ; -2542.51,-1009.88 -2429.55,-1337.47 ; -2532.51,-1009.88 -2419.55,-1337.47 ; -2527.11,-1019.54 -2015.57,-1019.54 ; -2522.51,-1009.88 -2409.55,-1337.47 ; -2512.51,-1009.88 -2399.55,-1337.47 ; -2507.51,-1009.88 -2394.55,-1337.47 ; -2499.55,-1009.54 -2385.79,-1339.43 ; -2250.57,-1254.43 -2041.72,-1013.44 ; -2250.57,-1239.43 -2041.72,-998.44 ; -2245.57,-1269.43 -2036.72,-1028.44 ; -2245.57,-1259.43 -2036.72,-1018.44 ; -2245.57,-1224.43 -2036.72,-983.44 ; -2243.43,-1276.96 -2036.72,-1038.44 ; -2242.73,-1207.57 -2033.87,-966.58 ; -2240.57,-1284.43 -2031.72,-1043.44 ; -2235.57,-1289.43 -2026.72,-1048.44 ; -2230.57,-1294.43 -2021.72,-1053.44 ; -2225.57,-1299.43 -2016.72,-1058.44 ; -2220.57,-1314.43 -2011.72,-1073.44 ; -2220.57,-1304.43 -2011.72,-1063.44 ; -2215.19,-1319.76 -2001.72,-1073.44 ; -2175.4,-1343.84 cw(c-2146.56,-1243.5) -2217.58,-1166.97 -2124.47,-1059.54 ccw(c-2137.47,-1041.35) -2138.5,-1019.01 ; -2111.57,-1210.79 ccw(c-2099.85,-1228.78) -2095.72,-1249.86 ; -2036.51,-855.56 cw(c-2027.2,-958.02) -1931.68,-919.81
  lines w11.81: -2477.76,-1339.43 -2385.79,-1339.43 ; -1699.78,-1500.47 -1699.78,-713.07 ; -1699.78,-1303.62 662.42,-1303.62 ; -1699.78,-1106.77 662.42,-1106.77 ; -1699.78,-909.92 662.42,-909.92 ; -912.38,-1500.47 -912.38,-909.92 ; -2880.88,-1500.47 -2880.88,-713.07 662.42,-713.07 662.42,-1500.47 -2880.88,-1500.47
  text "Project: '.Board_Name'" at 615.42,-839.69 h118.11
  text "Gerber:" at -958.95,-1039.84 h118.11
  text "Layer:" at 615.41,-1039.84 h118.11
  text "Ref: MB1716" at -958.95,-1236.69 h118.11
  text "Variant: '.VariantName'" at 615.42,-1236.69 h118.11
  text "R" at -2735.57,-1334.43 h60
  text "Rev: A" at -956.7,-1433.54 h118.11
  text "Date:13-01-21" at 615.42,-1433.54 h118.11
Mechanical 22:
  lines w7.87: -1152.32,580.51 -1152.32,880.51 -952.32,880.51 -952.32,580.51 -1152.32,580.51

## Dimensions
-2574.47,918.11 to -2728.21,1299.21 on M2-Board Dimensions
-2574.47,918.11 to -2806.95,1220.47 on M2-Board Dimensions
-2806.95,1220.47 to 0,1130.06 on M2-Board Dimensions
-2728.21,1299.21 to -2491.99,0 on M2-Board Dimensions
